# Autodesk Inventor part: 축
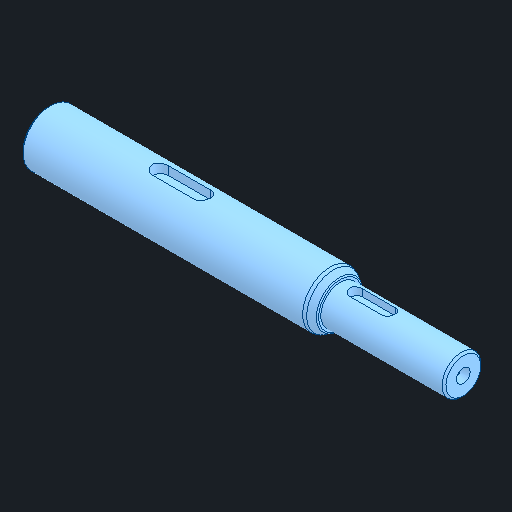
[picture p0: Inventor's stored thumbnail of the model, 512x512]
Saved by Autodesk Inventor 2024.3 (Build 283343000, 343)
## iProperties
Created: 2025-03
Part Number: 축
Material: 강철, 탄소
Document SubType Name: Modeling
Designer: user
Density: 7.85 g/cm^3
Appearance: 기본값
Author: jhkim
Sending System: Autodesk Inventor 2025
Preprocessor: ST-DEVELOPER v20
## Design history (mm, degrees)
feature "솔리드1"
node "솔리드2"
